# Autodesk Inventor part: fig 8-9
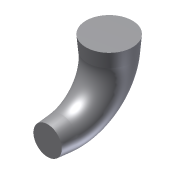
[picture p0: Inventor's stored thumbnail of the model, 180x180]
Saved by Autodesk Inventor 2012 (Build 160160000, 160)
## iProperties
Shininess: 77.0
Length Units: 11269
Angle Units: 11279
Time Units: 11290
Mass Units: 11283
Length Display Precision: 3
Angle Display Precision: 2
Created: 2001-12
Part Number: fig 8-9
Document SubType Name: Modeling
Designer: CADSoft
Density: 1 g/cm^3
Material: Default
Density: 0.0
Volumn: 0.0
Area: 0.0
PropertySet Name: Model Information
Control State: 0
Master: False
Checked Out: False
Author: CADSoft
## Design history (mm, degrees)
sketch "Sketch6"
  geometry: L1 (-48.928, -34.062)-(-33.928, -34.062); L2 (16.072, 15.938)-(16.072, 30.938); A1 r 50 centre (-33.928, 15.938) between (-33.928, -34.062) and (16.072, 15.938)
  constraints: 4 end point, 2 point on circle, 2 tangent, 1 centre point, 1 horizontal, 1 perpendicular
  dimensions: "d4" = 15 distance of L1.start L1.end; "d5" = 15 distance of L2.start L2.end; "d6" = 50 radius of A1
workplane "Work Plane1"
sketch "Sketch7"
  geometry: C1 r 15 at (0, 0)
  constraints: 1 centre point
  dimensions: "d7" = 30 diameter of C1
sweep "Sweep7" sketch "Sketch7" dims "d13" = 5 deg
body "Solid1"
